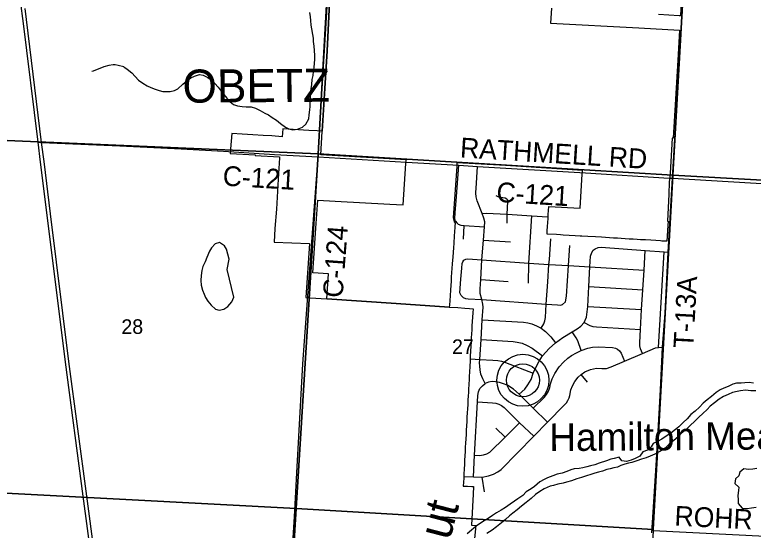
# Model space of a CAD drawing. Extents: x 114604 to 551442, y 316898 to 567001.
# Drawn here: x 204563 to 215723, y 344839 to 352635 of the extents above; entities that cross this region are included whole.
import ezdxf

# ---------------------------------------------------------------- set-up
doc = ezdxf.new("R2010")
doc.units = 0
for name, color, linetype in [('_CIVIL_CONSTRUCTION', 7, 'Continuous'), ('DV_X_County_Line', 7, 'Continuous'), ('GE_P_Alignment_1000_Cardinal_Points', 7, 'Continuous'), ('GE_P_Alignment_1000_Stations', 7, 'Continuous'), ('GE_P_Alignment_100_Stations', 7, 'Continuous'), ('GE_P_Alignment_500_Bearings', 7, 'Continuous'), ('GE_X_Alignment', 7, 'Continuous'), ('MT_X_Edge_Line', 7, 'Continuous'), ('PM_P_Cells', 7, 'Continuous'), ('PM_P_CL_Double_Solid', 7, 'Continuous'), ('PM_P_Crosswalk', 7, 'Continuous'), ('PM_X_Dotted_Line', 7, 'Continuous'), ('PV_X_Curb', 7, 'Continuous'), ('RD_P_GR_Rt', 7, 'Continuous'), ('SH_Named_Boundary', 7, 'Continuous'), ('SN_P_Signs', 7, 'Continuous')]:
    doc.layers.add(name, color=color, linetype=linetype)

msp = doc.modelspace()

# ---------------------------------------------------------------- linework, layer by layer
at = {"layer": 'DV_X_County_Line'}
for points in [[(215726, 347061), (215664, 347072), (215596, 347070), (215542, 347064), (215470, 347063), (215413, 347049), (215345, 347014), (215279, 346988), (215225, 346961), (215164, 346921), (215094, 346861), (215026, 346810), (214965, 346762), (214909, 346701), (214848, 346641), (214782, 346592), (214723, 346524), (214663, 346469), (214601, 346405), (214548, 346361), (214476, 346308), (214410, 346260), (214343, 346217), (214275, 346181), (214211, 346152), (214182, 346102), (214124, 346050), (214054, 346023), (214009, 345957), (213941, 345924), (213879, 345900), (213808, 345880), (213740, 345889), (213697, 345945), (213623, 345923), (213572, 345912), (213504, 345890), (213396, 345853), (213330, 345829), (213265, 345814), (213211, 345800), (213147, 345783), (213091, 345773), (213019, 345767), (212965, 345752), (212906, 345726), (212834, 345703), (212760, 345687), (212696, 345661), (212616, 345630), (212565, 345608), (212497, 345569), (212417, 345503), (212366, 345466), (212294, 345418), (212239, 345365), (212167, 345313), (212115, 345279), (212048, 345234), (211978, 345182), (211912, 345141), (211845, 345103), (211785, 345062), (211717, 345016), (211658, 344981), (211602, 344947), (211534, 344903), (211463, 344842), (211399, 344786)], [(215761, 346945), (215689, 346950), (215605, 346956), (215531, 346947), (215479, 346937), (215409, 346921), (215342, 346894), (215276, 346862), (215206, 346821), (215137, 346765), (215073, 346716), (215027, 346666), (214962, 346603), (214900, 346547), (214837, 346483), (214773, 346426), (214704, 346360), (214640, 346307), (214588, 346251), (214525, 346194), (214455, 346140), (214394, 346079), (214314, 346029), (214238, 345990), (214167, 345958), (214103, 345935), (214033, 345913), (213963, 345887), (213891, 345866), (213838, 345852), (213782, 345839), (213722, 345819), (213670, 345795), (213618, 345784), (213560, 345770), (213509, 345756), (213447, 345731), (213383, 345717), (213331, 345702), (213267, 345682), (213206, 345662), (213130, 345635), (213058, 345615), (212976, 345588), (212902, 345568), (212851, 345549), (212771, 345535), (212707, 345516), (212655, 345508), (212564, 345463), (212500, 345425), (212432, 345381), (212365, 345320), (212293, 345260), (212220, 345203), (212158, 345149), (212090, 345098), (212039, 345056), (211981, 345001), (211921, 344953), (211842, 344890), (211776, 344842), (211699, 344791)]]:
    msp.add_lwpolyline(points, dxfattribs=at)
at = {"layer": 'GE_P_Alignment_1000_Cardinal_Points'}
for p, q in [((211346, 349241), (211355, 349447)), ((211646, 349225), (212054, 349200)), ((214290, 347605), (214375, 349049)), ((211605, 348629), (212020, 348603)), ((213238, 348523), (214056, 348475)), ((213224, 348224), (214034, 348176)), ((213218, 347078), (213122, 347194)), ((211973, 346248), (211831, 346382)), ((211661, 345418), (211626, 345641))]:
    msp.add_line(p, q, dxfattribs=at)
for points in [[(211225, 349514), (211216, 349553), (211220, 349640), (211239, 349885), (211272, 350360)], [(211671, 347060), (211636, 347130), (211608, 347202), (211596, 347264), (211590, 347319), (211586, 347369), (211593, 347422), (211610, 347723), (211627, 348020), (211642, 348215), (211638, 348259), (211620, 348329), (211597, 348421), (211594, 348489), (211605, 348629), (211624, 348927), (211646, 349225), (211660, 349427), (211666, 349504), (211654, 349561), (211628, 349627), (211550, 349823), (211535, 349881), (211531, 349935), (211531, 349951), (211535, 350009), (211558, 350342)], [(212005, 349482), (212007, 349617), (212017, 349811), (212013, 349831), (211999, 349845), (211976, 349862), (211937, 349868), (211881, 349875), (211836, 349895)], [(211628, 349627), (211687, 349635), (212007, 349617), (212378, 349594), (212615, 349580)], [(212327, 348576), (212331, 348880), (212378, 349594)], [(211225, 349514), (211242, 349486), (211262, 349469), (211304, 349454), (211355, 349447), (211660, 349427)], [(212520, 347894), (212561, 347962), (212576, 348006), (212584, 348058), (212593, 348258), (212621, 348596), (212633, 348859), (212645, 348933), (212665, 349247)], [(212841, 348255), (212885, 348292), (212901, 348377), (212932, 348844), (212951, 349146)], [(213305, 349073), (213332, 349093), (213380, 349115), (213424, 349118), (214088, 349071), (214375, 349049), (214436, 349047)], [(212186, 346895), (212269, 346974), (212319, 347036), (212365, 347117), (212399, 347213), (212443, 347310), (212487, 347395), (212540, 347477), (212638, 347588), (212733, 347671), (212846, 347752), (212987, 347838), (213061, 347884), (213119, 347926), (213169, 347982), (213202, 348061), (213224, 348224), (213238, 348523), (213253, 348822), (213264, 348983), (213283, 349041), (213305, 349073)], [(214051, 347514), (214022, 347583), (214012, 347628), (214009, 347680), (214019, 347877), (214034, 348176), (214056, 348475), (214073, 348774), (214088, 349071)], [(211340, 348358), (211308, 348387), (211290, 348430), (211306, 348638), (211318, 348802), (211325, 348872), (211334, 348897), (211351, 348922)], [(211351, 348922), (211380, 348938), (211408, 348943), (211624, 348927), (212331, 348880), (212633, 348859), (212932, 348844), (213253, 348822), (214073, 348774)], [(211340, 348358), (211375, 348343), (211413, 348339), (211620, 348329), (212593, 348258), (212766, 348249), (212810, 348245), (212841, 348255)], [(211627, 348020), (212253, 347988), (212315, 347978), (212379, 347963), (212450, 347932), (212520, 347894), (212586, 347844), (212663, 347765), (212733, 347671)], [(213169, 347982), (213252, 347934), (213299, 347918), (213357, 347913), (214019, 347877)], [(213125, 347558), (213072, 347703), (213045, 347749), (212987, 347838)], [(211610, 347723), (212093, 347695), (212158, 347686), (212231, 347666), (212308, 347635), (212380, 347595), (212540, 347477)], [(211350, 345654), (211494, 345645), (211626, 345641), (211720, 345661), (211797, 345686), (211862, 345721), (211916, 345759), (212407, 346261), (212614, 346474), (212868, 346733), (212901, 346768), (212923, 346800), (212942, 346840), (212953, 346878), (212969, 346964), (212992, 347025), (213027, 347091), (213080, 347156), (213122, 347194), (213179, 347233), (213262, 347268), (213354, 347291), (213437, 347284), (213508, 347287), (213578, 347312), (213779, 347398), (214051, 347514), (214245, 347598), (214290, 347605), (214354, 347606)], [(212399, 346683), (212565, 346849), (212601, 346893), (212630, 346944), (212648, 346996), (212661, 347054), (212687, 347128), (212726, 347209), (212791, 347309), (212856, 347380), (212922, 347442), (212978, 347481), (213053, 347524), (213125, 347558), (213225, 347592), (213292, 347606), (213378, 347611), (213594, 347603), (213644, 347594), (213674, 347580), (213704, 347553), (213726, 347516), (213779, 347398)], [(211449, 347432), (211593, 347422), (211789, 347413), (211865, 347406), (211920, 347394), (211978, 347375), (212399, 347213)], [(212614, 346474), (212399, 346683), (212186, 346895), (212099, 346972), (212016, 347026), (211966, 347048), (211887, 347074), (211826, 347085), (211776, 347091), (211724, 347081), (211671, 347060)], [(211494, 345645), (211511, 345976), (211556, 346781), (211561, 346876), (211572, 346933), (211592, 346983), (211630, 347025), (211671, 347060)], [(211556, 346781), (211782, 346767), (211833, 346759), (211877, 346745), (211917, 346726), (211957, 346695), (212190, 346466), (212407, 346261)], [(211511, 345976), (211587, 345972), (211646, 345979), (211698, 345994), (211745, 346020), (211973, 346248), (212190, 346466)]]:
    msp.add_lwpolyline(points, dxfattribs=at)
at = {"layer": 'GE_P_Alignment_1000_Stations'}
for points in [[(204683, 352579), (204660, 352770), (204646, 352938), (204637, 353113), (204634, 353287), (204642, 353450), (204651, 353595), (204665, 353720), (204679, 353824), (204697, 353936), (204728, 354091), (204770, 354256), (204822, 354437), (204930, 354781), (205038, 355122)], [(206182, 340326), (206196, 340477), (206208, 340636), (206209, 340798), (206208, 340976), (206197, 341181), (206152, 341582), (206097, 341982), (205970, 342969), (205872, 343691), (205768, 344484), (205650, 345353), (205382, 347391), (205104, 349623), (205005, 350415), (204967, 350703), (204739, 352561), (204719, 352732)], [(206124, 340251), (206128, 340293), (206152, 340637), (206157, 340746), (206157, 340864), (206154, 341016), (206143, 341181), (206098, 341580), (206046, 341986), (205916, 342960), (205824, 343668), (205718, 344453), (205599, 345356), (205331, 347383), (205052, 349604), (204952, 350404), (204916, 350706), (204688, 352542), (204683, 352579)]]:
    msp.add_lwpolyline(points, dxfattribs=at)
at = {"layer": 'GE_P_Alignment_100_Stations'}
for points in [[(209334, 353130), (209310, 352611), (209282, 352090), (209208, 350873), (209133, 350878), (209007, 350886), (208613, 350910), (208605, 350791), (208446, 350804), (208319, 350811), (208160, 350821), (208002, 350831), (207842, 350841), (207823, 350609), (207822, 350599), (207817, 350537), (208198, 350516), (208197, 350504), (208564, 350484), (208564, 350473), (208544, 350150), (208516, 349696), (208495, 349404), (208481, 349197), (209018, 349174), (208964, 348360), (209029, 348354), (209278, 348338), (210329, 348268), (211129, 348215), (211260, 348206), (211366, 348199), (211436, 348194), (211489, 348190), (211485, 348125), (211481, 348060), (211477, 347996), (211473, 347931), (211469, 347868), (211465, 347809), (211461, 347748), (211458, 347690), (211454, 347620), (211451, 347550), (211447, 347468), (211444, 347408), (211439, 347312), (211435, 347239), (211430, 347159), (211428, 347110), (211425, 347056), (211420, 346960), (211418, 346924), (211415, 346872), (211411, 346806), (211408, 346742), (211404, 346677), (211401, 346613), (211397, 346547), (211394, 346483), (211390, 346418), (211387, 346353), (211383, 346289), (211380, 346224), (211376, 346158), (211372, 346094), (211369, 346028), (211365, 345964), (211362, 345900), (211358, 345834), (211355, 345769), (211350, 345688), (211348, 345628), (211341, 345508), (211405, 345504), (211471, 345500), (211498, 345499), (211492, 345384), (211467, 344915), (211531, 344912), (211509, 344712)], [(212675, 352737), (212660, 352509), (213996, 352437), (214610, 352404), (214584, 351948), (214514, 350769), (214500, 350770), (214469, 350240), (214455, 350101), (214448, 349921), (214426, 349512), (214437, 349511), (214433, 349446), (214419, 349209), (214408, 349209), (214359, 349212), (214342, 349213), (214322, 349215), (214249, 349219), (214174, 349224), (214094, 349229), (214030, 349233), (214019, 349233), (213970, 349236), (213910, 349240), (213850, 349243), (213790, 349247), (213729, 349251), (213670, 349254), (213611, 349258), (213552, 349262), (213491, 349265), (213431, 349269), (213337, 349275), (213223, 349282), (213131, 349287), (213110, 349288), (213030, 349293), (212852, 349304), (212812, 349307), (212751, 349310), (212608, 349319), (212611, 349368), (212615, 349433), (212623, 349554), (212626, 349614), (212634, 349734), (213107, 349708), (213138, 350222), (213142, 350281), (211978, 350353), (211246, 350395), (211242, 350340), (211190, 349568), (211204, 349501), (211218, 349482), (211213, 349436), (211212, 349423), (211208, 349354), (211203, 349291), (211196, 349181), (211191, 349112), (211181, 348973), (211174, 348866), (211169, 348799), (211165, 348735), (211160, 348669), (211156, 348605), (211152, 348540), (211147, 348475), (211141, 348382), (211131, 348245), (211129, 348215), (210329, 348268), (209278, 348338), (209302, 348717), (209069, 348732), (209089, 349031), (209100, 349181), (209115, 349408), (209144, 349829), (209404, 349815), (210232, 349771), (210431, 349760), (210475, 350385), (210480, 350440), (209186, 350516), (209208, 350871), (209282, 352089), (209310, 352610), (209334, 353130)], [(214635, 352837), (214622, 352619), (214602, 352620), (214293, 352639)]]:
    msp.add_lwpolyline(points, dxfattribs=at)
at = {"layer": 'GE_P_Alignment_500_Bearings'}
for p, q in [((214503, 350163), (214666, 352884)), ((209148, 350486), (209170, 350853)), ((208993, 348382), (209148, 350486)), ((210476, 350407), (211272, 350360)), ((213189, 350243), (214451, 350166)), ((214451, 350166), (214503, 350163))]:
    msp.add_line(p, q, dxfattribs=at)
for points in [[(209170, 350853), (209329, 353508), (209330, 353634)], [(204916, 350706), (204967, 350703), (206149, 350655), (207078, 350609), (207718, 350570)], [(207718, 350570), (208490, 350523), (209148, 350486), (210476, 350407)], [(211272, 350360), (211558, 350342), (213189, 350243)], [(214354, 347606), (214392, 348123), (214436, 349047), (214503, 350163)], [(214503, 350163), (216273, 350057), (218053, 349965), (218159, 349962)], [(208628, 342485), (208628, 342490), (208790, 345040), (208827, 345709), (208918, 347356), (208993, 348382)], [(214285, 346336), (214321, 346965), (214354, 347606)], [(214191, 344801), (214255, 345818), (214285, 346336)]]:
    msp.add_lwpolyline(points, dxfattribs=at)
at = {"layer": 'GE_X_Alignment'}
for radius in [393, 249]:
    msp.add_circle((212242, 347107), radius, dxfattribs=at)
at = {"layer": 'MT_X_Edge_Line'}
for points in [[(207774, 348780), (207782, 348832), (207792, 348886), (207803, 348938), (207783, 349012), (207764, 349090), (207734, 349140), (207655, 349189), (207591, 349169), (207536, 349110), (207508, 349058), (207467, 348964), (207439, 348898), (207406, 348826), (207390, 348766), (207380, 348694), (207375, 348618), (207381, 348546), (207398, 348468), (207426, 348410), (207447, 348357), (207479, 348303), (207530, 348241), (207596, 348182), (207652, 348168), (207720, 348181), (207782, 348223), (207844, 348291), (207875, 348362)], [(207875, 348362), (207774, 348780)], [(215776, 345774), (215716, 345764), (215652, 345756), (215580, 345769), (215521, 345715), (215505, 345661), (215453, 345617), (215446, 345547), (215504, 345491), (215502, 345439), (215489, 345367), (215497, 345297), (215498, 345243), (215554, 345174), (215632, 345168), (215696, 345179), (215766, 345189)]]:
    msp.add_lwpolyline(points, dxfattribs=at)
at = {"layer": 'PM_P_Cells'}
for points in [[(206209, 351846), (206264, 351813), (206334, 351755), (206383, 351700), (206433, 351648), (206498, 351601), (206564, 351558), (206619, 351536), (206685, 351509), (206743, 351488), (206803, 351476), (206859, 351473), (206913, 351473), (206977, 351490), (207029, 351516), (207104, 351583), (207158, 351633), (207222, 351680), (207277, 351706), (207355, 351729), (207409, 351720), (207482, 351688), (207538, 351645), (207587, 351594), (207639, 351538), (207682, 351481), (207722, 351427), (207769, 351374), (207816, 351320), (207870, 351279), (207930, 351257), (208000, 351248), (208061, 351245), (208135, 351243), (208199, 351224), (208273, 351189), (208340, 351149), (208398, 351124), (208454, 351083), (208517, 351039), (208581, 350990), (208652, 350933), (208704, 350909), (208764, 350896), (208834, 350903), (208910, 350935), (208964, 350978), (209005, 351062), (209011, 351120), (209022, 351196), (209025, 351246), (209029, 351316), (209030, 351380), (209033, 351444), (209041, 351516), (209050, 351582), (209059, 351656), (209071, 351718), (209080, 351778), (209086, 351838), (209093, 351904), (209096, 351960), (209096, 352021), (209091, 352095), (209088, 352161), (209080, 352229), (209077, 352279), (209067, 352337), (209052, 352420), (209043, 352478), (209037, 352546), (209032, 352604), (209020, 352670)], [(206209, 351846), (206126, 351869), (206078, 351880), (206048, 351878), (205982, 351870), (205911, 351845), (205749, 351782), (205729, 351777)]]:
    msp.add_lwpolyline(points, dxfattribs=at)
at = {"layer": 'PM_X_Dotted_Line'}
msp.add_line((212242, 347107), (212242, 347107), dxfattribs=at)
at = {"layer": 'SN_P_Signs'}
for points in [[(209446, 355851), (209148, 350532), (203855, 350761), (204167, 356134)], [(209446, 355851), (214813, 355546), (214507, 350209), (209148, 350532)], [(214813, 355546), (220066, 355223), (219745, 349915), (214507, 350209)], [(203855, 350761), (209148, 350532), (208815, 345168), (203568, 345444)], [(209148, 350532), (214507, 350209), (214212, 344849), (208815, 345168)], [(214507, 350209), (219745, 349915), (219405, 344570), (214210, 344829), (214212, 344849)], [(208815, 345168), (214212, 344849), (214210, 344829), (213887, 339536), (208486, 339851)]]:
    msp.add_lwpolyline(points, close=True, dxfattribs=at)
msp.add_lwpolyline([(203568, 345444), (208815, 345168), (208486, 339851), (204088, 340018)], dxfattribs=at)

# ---------------------------------------------------------------- texts
at = {"layer": '_CIVIL_CONSTRUCTION'}
msp.add_text('Hamilton Meadows', height=417.03, rotation=0.4135, dxfattribs=at).set_placement((212643, 346036))
at = {"layer": 'PM_P_CL_Double_Solid'}
for s, height, rotation, p in [('RATHMELL RD', 300.02, 356.446, (211286, 350479)), ('C-121', 300, 356.5628, (207699, 350052)), ('C-121', 300, 356.5234, (211836, 349806)), ('C-124', 300, 85.718, (209516, 348347)), ('ROHR', 300, 357.2063, (214528, 344909))]:
    msp.add_text(s, height=height, rotation=rotation, dxfattribs=at).set_placement(p)
at = {"layer": 'PM_P_Crosswalk'}
msp.add_text('T-13A', height=300, rotation=86.8051, dxfattribs=at).set_placement((214816, 347585))
at = {"layer": 'PV_X_Curb'}
for s, rotation, p in [('28', 0.4134, (206175, 347807)), ('27', 0.4135, (211172, 347504))]:
    msp.add_text(s, height=221, rotation=rotation, dxfattribs=at).set_placement(p)
at = {"layer": 'RD_P_GR_Rt'}
msp.add_text('Walnut', height=500, rotation=75.4142, dxfattribs=at).set_placement((210755, 343203))
at = {"layer": 'SH_Named_Boundary'}
msp.add_text('OBETZ', height=500, rotation=0.4134, dxfattribs=at).set_placement((207100, 351304))

doc.saveas('drawing.dxf')
